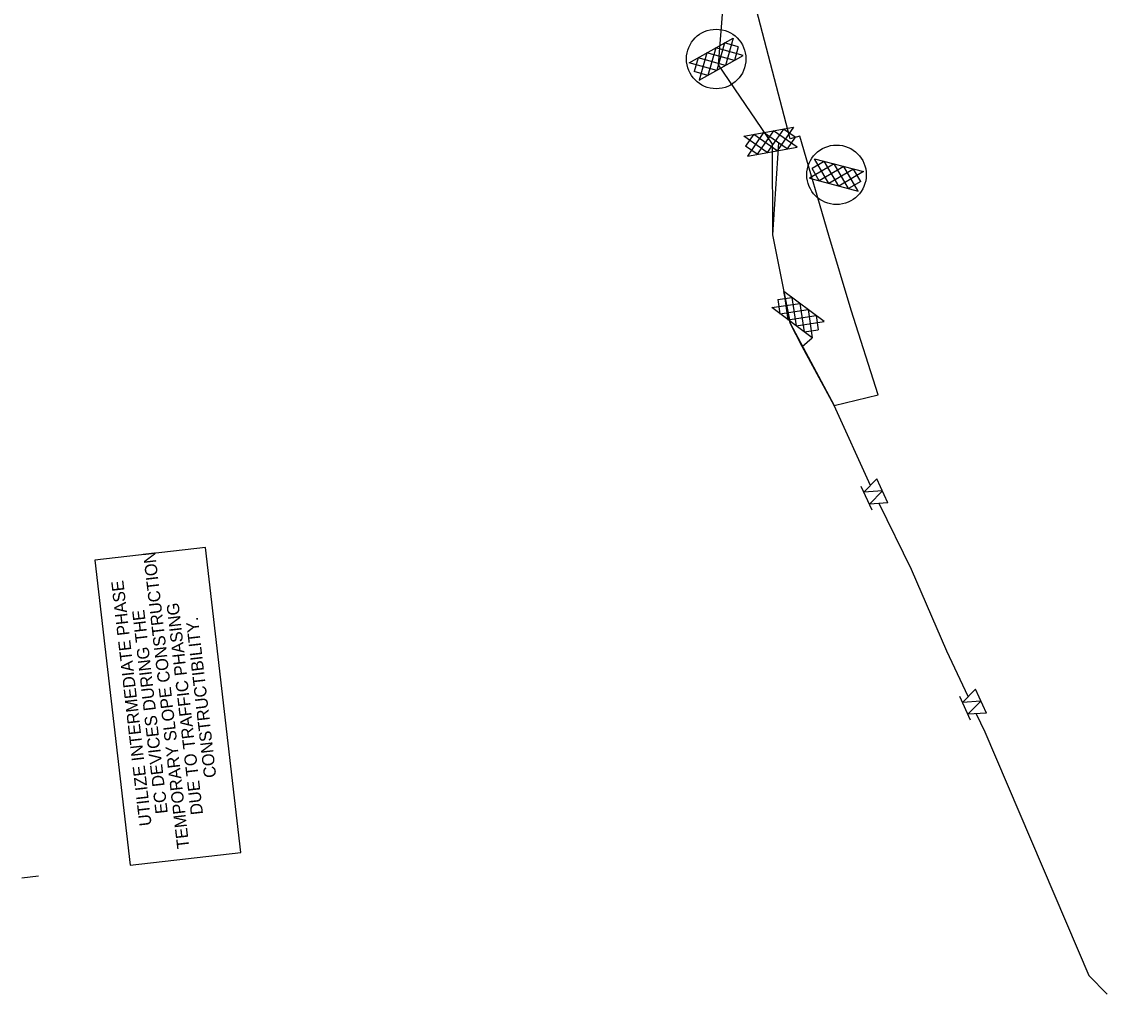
# Model space of a CAD drawing. Extents: x 400935 to 481562, y 415700 to 505362.
# Drawn here: x 477944 to 478566, y 494639 to 495196 of the extents above; entities that cross this region are included whole.
import ezdxf

# ---------------------------------------------------------------- set-up
doc = ezdxf.new("R2010")
doc.units = 0
for name, color, linetype in [('Matting on Slope Note Final CELL', 7, 'Continuous'), ('Old_Level_2', 7, 'Continuous'), ('Rock Silt Check Type A CG CELL', 7, 'Continuous'), ('Rock Silt Check Type A Final CELL', 7, 'Continuous'), ('Rock Silt Check Type A with Matting and PAM CG CELL', 7, 'Continuous'), ('Rock Silt Check Type A with Matting and PAM Final CELL', 7, 'Continuous'), ('Special Sediment Control Fence Section Both CELL', 7, 'Continuous'), ('Temporary Silt Fence Both', 7, 'Continuous'), ('Temporary Silt Fence CG', 7, 'Continuous'), ('Temporary Silt Fence Final', 7, 'Continuous')]:
    doc.layers.add(name, color=color, linetype=linetype)

msp = doc.modelspace()

# ---------------------------------------------------------------- linework, layer by layer
at = {"layer": 'Matting on Slope Note Final CELL'}
for p, q in [((478347.43, 495222.57), (478343.35, 495171.12)), ((478343.35, 495171.12), (478374.25, 495125.72))]:
    msp.add_line(p, q, dxfattribs=at)
msp.add_lwpolyline([(478374.25, 495125.72), (478374.45, 495073.79), (478384.67, 495023.15), (478409.74, 494976.07), (478435.04, 494982.2), (478419.59, 495030.62), (478406.69, 495073.26), (478390.07, 495130.13), (478384.59, 495128.7), (478372.25, 495176.12), (478359.62, 495224.67)], dxfattribs=at)
at = {"layer": 'Old_Level_2'}
msp.add_lwpolyline([(478069.98, 494720.13), (478049.76, 494894.7), (477986.27, 494887.35), (478006.49, 494712.78)], close=True, dxfattribs=at)
at = {"layer": 'Rock Silt Check Type A CG CELL'}
for p, q in [((478380.96, 495041.28), (478383.32, 495025.12)), ((478404.14, 495024.02), (478380.96, 495041.28)), ((478374.06, 495032.02), (478390.22, 495034.38)), ((478397.24, 495014.76), (478374.06, 495032.02)), ((478377.48, 495036.64), (478385.61, 495037.82)), ((478377.48, 495036.64), (478378.7, 495028.54)), ((478385.61, 495037.82), (478387.97, 495021.65)), ((478390.22, 495034.38), (478392.63, 495018.19)), ((478378.7, 495028.54), (478394.87, 495030.92)), ((478383.32, 495025.12), (478399.52, 495027.45)), ((478394.87, 495030.92), (478397.24, 495014.76)), ((478399.52, 495027.45), (478400.68, 495019.36)), ((478387.97, 495021.65), (478404.14, 495024.02)), ((478392.7, 495018.2), (478400.68, 495019.36))]:
    msp.add_line(p, q, dxfattribs=at)
at = {"layer": 'Rock Silt Check Type A Final CELL'}
for p, q in [((478358.07, 495130.22), (478386.52, 495135.29)), ((478369.44, 495132.25), (478360.09, 495118.85)), ((478375.15, 495133.27), (478365.75, 495119.86)), ((478382.83, 495122.9), (478369.44, 495132.25)), ((478380.81, 495134.29), (478371.46, 495120.88)), ((478388.54, 495123.92), (478375.15, 495133.27)), ((478386.52, 495135.29), (478377.17, 495121.89)), ((478387.54, 495129.63), (478380.81, 495134.29)), ((478371.46, 495120.88), (478358.07, 495130.22)), ((478363.69, 495131.17), (478359.06, 495124.56)), ((478377.17, 495121.89), (478363.73, 495131.23)), ((478387.54, 495129.63), (478382.83, 495122.9)), ((478365.75, 495119.86), (478359.06, 495124.56)), ((478360.09, 495118.85), (478388.54, 495123.92))]:
    msp.add_line(p, q, dxfattribs=at)
at = {"layer": 'Rock Silt Check Type A with Matting and PAM CG CELL'}
for p, q in [((478409.78, 495114.32), (478395.66, 495106.11)), ((478404.11, 495115.77), (478397.13, 495111.72)), ((478398.61, 495117.27), (478426.55, 495109.89)), ((478406.83, 495103.16), (478398.61, 495117.27)), ((478415.39, 495112.84), (478401.22, 495104.64)), ((478412.44, 495101.67), (478404.17, 495115.8)), ((478418, 495100.21), (478409.78, 495114.32)), ((478423.6, 495098.72), (478415.39, 495112.84)), ((478401.22, 495104.64), (478397.13, 495111.72)), ((478420.95, 495111.38), (478406.83, 495103.16)), ((478426.55, 495109.89), (478412.44, 495101.67)), ((478425.1, 495104.33), (478420.95, 495111.38)), ((478395.66, 495106.11), (478423.6, 495098.72)), ((478425.1, 495104.33), (478418, 495100.21))]:
    msp.add_line(p, q, dxfattribs=at)
msp.add_circle((478411.18, 495108.11), 17.04, dxfattribs=at)
at = {"layer": 'Rock Silt Check Type A with Matting and PAM Final CELL'}
for p, q in [((478326.84, 495172.28), (478352.06, 495186.38)), ((478346.99, 495183.56), (478342.56, 495167.84)), ((478354.88, 495181.37), (478346.99, 495183.56)), ((478352.06, 495186.38), (478347.62, 495170.67)), ((478354.88, 495181.37), (478352.64, 495173.47)), ((478331.84, 495175.02), (478329.63, 495167.25)), ((478347.62, 495170.67), (478331.86, 495175.09)), ((478336.92, 495177.92), (478332.48, 495162.2)), ((478332.48, 495162.2), (478357.7, 495176.3)), ((478352.64, 495173.47), (478336.92, 495177.92)), ((478341.98, 495180.75), (478337.49, 495165)), ((478357.7, 495176.3), (478341.98, 495180.75)), ((478342.56, 495167.84), (478326.84, 495172.28)), ((478337.49, 495165), (478329.63, 495167.25)), ((477944.44, 494705.58), (477954.08, 494706.7))]:
    msp.add_line(p, q, dxfattribs=at)
msp.add_circle((478342.24, 495174.42), 17.04, dxfattribs=at)
at = {"layer": 'Special Sediment Control Fence Section Both CELL'}
for p, q in [((478440.66, 494920.31), (478434.35, 494933.92)), ((478431.59, 494916.1), (478425.28, 494929.71)), ((478487.91, 494795.79), (478481.72, 494809.46)), ((478497.02, 494799.92), (478490.83, 494813.58))]:
    msp.add_line(p, q, dxfattribs=at)
for points in [[(478437.5, 494927.11), (478426.86, 494926.3), (478434.35, 494933.92)], [(478440.66, 494920.31), (478430.01, 494919.5), (478437.5, 494927.11)], [(478493.93, 494806.75), (478483.27, 494806.04), (478490.83, 494813.58)], [(478497.02, 494799.92), (478486.36, 494799.21), (478493.93, 494806.75)]]:
    msp.add_lwpolyline(points, dxfattribs=at)
at = {"layer": 'Temporary Silt Fence Both'}
for points in [[(478430.7, 494930.21), (478409.74, 494976.07), (478391.55, 495009.84)], [(478486.65, 494809.41), (478474.45, 494835.28), (478454.09, 494882.17), (478435.67, 494919.93)], [(478491.24, 494799.53), (478496.13, 494789.11), (478555.69, 494649.66), (478566.27, 494638.89)]]:
    msp.add_lwpolyline(points, dxfattribs=at)
at = {"layer": 'Temporary Silt Fence CG'}
msp.add_line((478391.55, 495009.84), (478397.24, 495014.76), dxfattribs=at)
at = {"layer": 'Temporary Silt Fence Final'}
for points in [[(478378.03, 495126.37), (478374.45, 495073.79), (478380.96, 495041.28), (478380.96, 495041.28)], [(478391.55, 495009.84), (478384.67, 495023.15), (478380.96, 495041.28)]]:
    msp.add_lwpolyline(points, dxfattribs=at)

# ---------------------------------------------------------------- texts
at = {"layer": 'Old_Level_2'}
for s, p in [('TEMPORARY SLOPE CONSTRUCTION', (478040.51, 494722.68)), ('UTILIZE INTERMEDIATE PHASE', (478018.88, 494735.62)), ('EC DEVICES DURING THE ', (478028.13, 494742.62)), ('DUE TO TRAFFIC PHASING', (478048.33, 494742.03)), ('CONSTRUCTIBILITY.', (478055.94, 494763.22))]:
    msp.add_text(s, height=7, rotation=96.60681, dxfattribs=at).set_placement(p)

doc.saveas('drawing.dxf')
